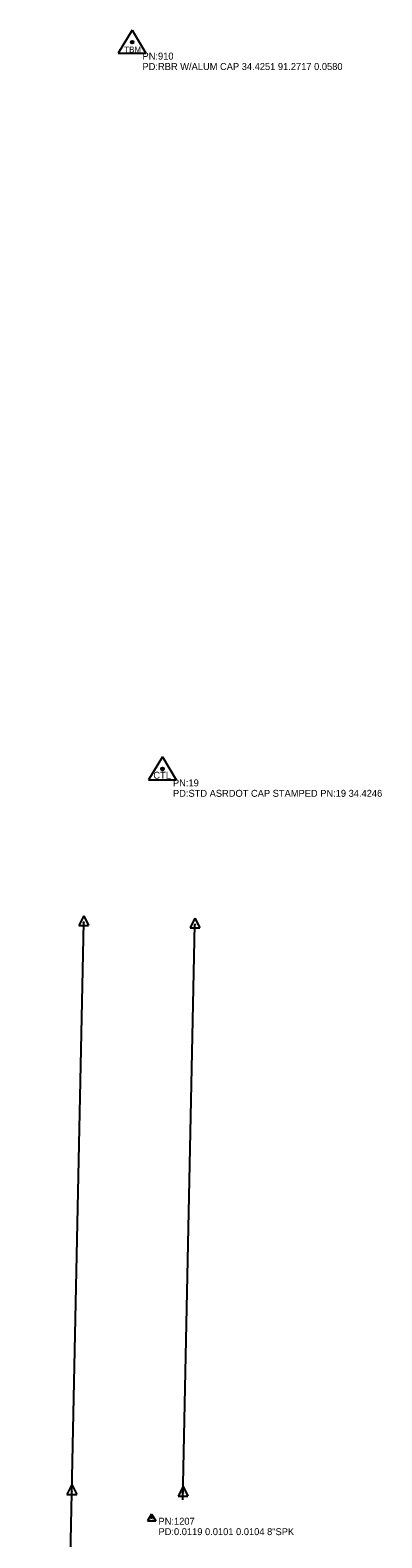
# Model space of a CAD drawing. Extents: x 1443798 to 1476449, y 2041559 to 2057889.
# Drawn here: x 1476196 to 1476449, y 2056805 to 2057889 of the extents above; entities that cross this region are included whole.
import ezdxf

# ---------------------------------------------------------------- set-up
doc = ezdxf.new("R2010")
doc.units = 0
for name, color, linetype in [('S_EXIST_ROW', 7, 'Continuous'), ('S_EXIST_ROW_ANNOT', 7, 'Continuous'), ('S_PRIMARY_CTL', 7, 'Continuous'), ('S_PRIMARY_CTL_ANNOT', 7, 'Continuous'), ('S_SECONDARY_CTL', 7, 'Continuous'), ('S_SECONDARY_CTL_ANNOT', 7, 'Continuous')]:
    doc.layers.add(name, color=color, linetype=linetype)

msp = doc.modelspace()

# ---------------------------------------------------------------- linework, layer by layer
at = {"layer": 'S_EXIST_ROW'}
for p, q in [((1476196, 2055396.5), (1476234.5, 2057247.2)), ((1476305.9, 2056831.9), (1476314.5, 2057245.6))]:
    msp.add_line(p, q, dxfattribs=at)
at = {"layer": 'S_EXIST_ROW_ANNOT'}
for p, q in [((1476234.5, 2057252), (1476231, 2057244.9)), ((1476234.5, 2057252), (1476238, 2057244.9)), ((1476314.5, 2057250.3), (1476311, 2057243.2)), ((1476314.5, 2057250.3), (1476318, 2057243.2)), ((1476231, 2057244.9), (1476238, 2057244.9)), ((1476234.5, 2057247.2), (1476234.5, 2057247.2)), ((1476311, 2057243.2), (1476318, 2057243.2)), ((1476314.5, 2057245.6), (1476314.5, 2057245.6)), ((1476226, 2056842.8), (1476222.5, 2056835.7)), ((1476226, 2056842.8), (1476229.5, 2056835.7)), ((1476226, 2056838.1), (1476226, 2056838.1)), ((1476306, 2056841.5), (1476302.5, 2056834.4)), ((1476306, 2056841.5), (1476309.5, 2056834.4)), ((1476306, 2056836.8), (1476306, 2056836.8)), ((1476222.5, 2056835.7), (1476229.5, 2056835.7)), ((1476302.5, 2056834.4), (1476309.5, 2056834.4))]:
    msp.add_line(p, q, dxfattribs=at)
for centre, radius in [((1476234.5, 2057247.2), 0.12), ((1476234.5, 2057247.2), 0.06), ((1476314.5, 2057245.6), 0.12), ((1476314.5, 2057245.6), 0.06), ((1476226, 2056838.1), 0.06), ((1476226, 2056838.1), 0.12), ((1476306, 2056836.8), 0.06), ((1476306, 2056836.8), 0.12)]:
    msp.add_circle(centre, radius, dxfattribs=at)
at = {"layer": 'S_PRIMARY_CTL'}
for p, q in [((1476269.3, 2057888.9), (1476259.3, 2057872.4)), ((1476269.3, 2057888.9), (1476279.2, 2057872.4)), ((1476259.3, 2057872.4), (1476279.2, 2057872.4)), ((1476291.2, 2057366.2), (1476281.2, 2057349.7)), ((1476291.2, 2057366.2), (1476301, 2057349.7)), ((1476281.2, 2057349.7), (1476301, 2057349.7))]:
    msp.add_line(p, q, dxfattribs=at)
for centre, radius in [((1476269.3, 2057880.2), 1.04), ((1476269.3, 2057880.2), 0.609), ((1476269.3, 2057880.2), 0.344), ((1476291.2, 2057357.5), 1.04), ((1476291.2, 2057357.5), 0.609), ((1476291.2, 2057357.5), 0.344)]:
    msp.add_circle(centre, radius, dxfattribs=at)
at = {"layer": 'S_SECONDARY_CTL'}
for p, q in [((1476283.3, 2056821.6), (1476280.3, 2056816.7)), ((1476280.3, 2056816.7), (1476286.3, 2056816.7)), ((1476283.3, 2056821.6), (1476286.3, 2056816.7))]:
    msp.add_line(p, q, dxfattribs=at)
for radius in [0.311, 0.183, 0.103]:
    msp.add_circle((1476283.3, 2056819), radius, dxfattribs=at)

# ---------------------------------------------------------------- texts
at = {"layer": 'S_PRIMARY_CTL'}
msp.add_text('TBM', height=4.29, rotation=360, dxfattribs=at).set_placement((1476263.7, 2057872.8))
msp.add_text('CTL', height=5, dxfattribs=at).set_placement((1476284.6, 2057350.5))
at = {"layer": 'S_PRIMARY_CTL_ANNOT'}
for s, p in [('PN:910', (1476276.8, 2057867.7)), ('PD:RBR W/ALUM CAP 34.4251 91.2717 0.0580', (1476276.8, 2057860.2)), ('PN:19', (1476298.7, 2057345)), ('PD:STD ASRDOT CAP STAMPED PN:19 34.4246', (1476298.7, 2057337.5))]:
    msp.add_text(s, height=5, dxfattribs=at).set_placement(p)
at = {"layer": 'S_SECONDARY_CTL'}
msp.add_text('TV', height=1.5, dxfattribs=at).set_placement((1476282.1, 2056817))
at = {"layer": 'S_SECONDARY_CTL_ANNOT'}
for s, p in [('PN:1207', (1476288.3, 2056814)), ('PD:0.0119 0.0101 0.0104 8"SPK', (1476288.3, 2056806.5))]:
    msp.add_text(s, height=5, dxfattribs=at).set_placement(p)

doc.saveas('drawing.dxf')
